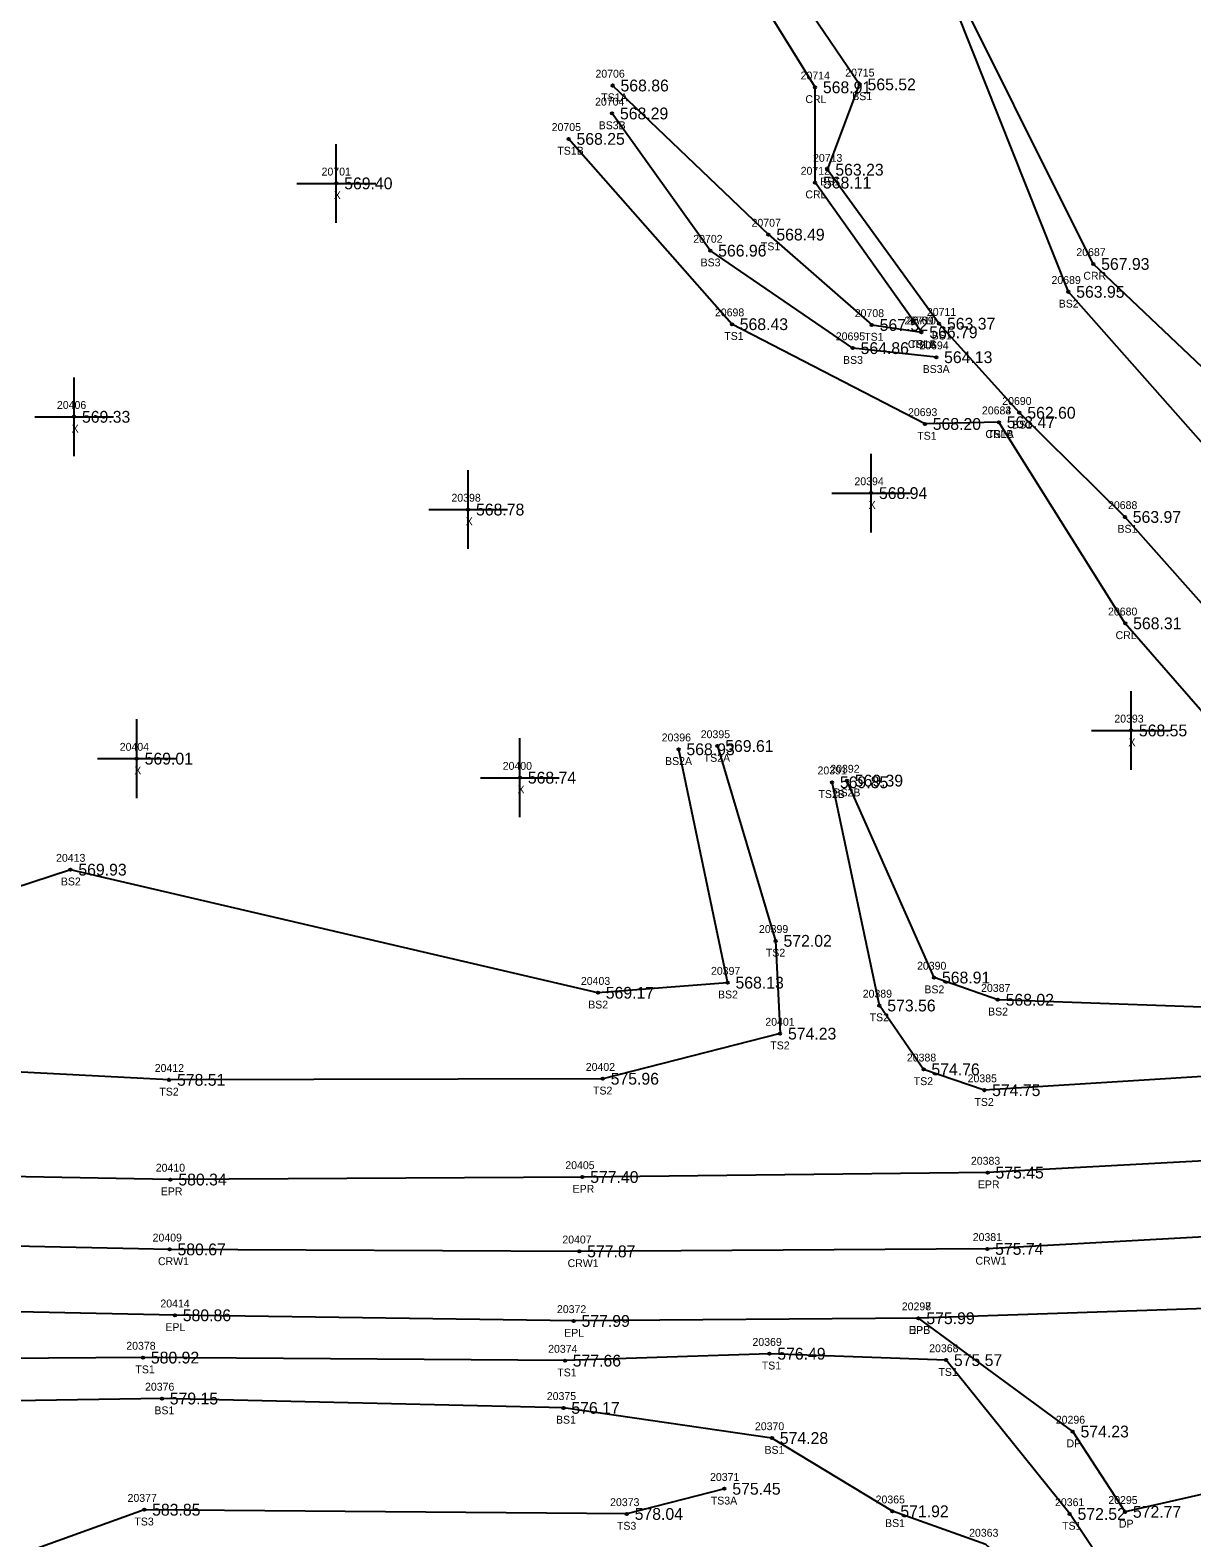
# Model space of a CAD drawing. Extents: x 1530159 to 1531652, y 877045 to 877724.
# Drawn here: x 1530693.4 to 1530840.9, y 877231.5 to 877423 of the extents above; entities that cross this region are included whole.
import ezdxf

# ---------------------------------------------------------------- set-up
doc = ezdxf.new("R2010")
doc.units = 0
for name, color, linetype in [('RD_DTM_BkLn1', 7, 'Continuous'), ('RD_DTM_BkLn2', 7, 'Continuous'), ('RD_DTM_BkLn_txCode', 7, 'Continuous'), ('RD_EX_Driveway', 7, 'Continuous'), ('RD_EX_Driveway_txCode', 7, 'Continuous'), ('RD_EX_H2O', 7, 'Continuous'), ('RD_EX_H2O_txCode', 7, 'Continuous'), ('RD_EX_Misc', 7, 'Continuous'), ('RD_EX_Misc_txCode', 7, 'Continuous'), ('RD_EX_Road', 7, 'Continuous'), ('RD_EX_Road_txCode', 7, 'Continuous'), ('RD_EX_TX_Driveway_ELEV', 7, 'Continuous'), ('RD_EX_TX_H2O_ELEV', 7, 'Continuous'), ('RD_EX_TX_Misc_ELEV', 7, 'Continuous'), ('RD_EX_TX_Road_ELEV', 7, 'Continuous'), ('RD_HC_Survey_ELEV', 7, 'Continuous'), ('RD_HC_Survey_txCode', 7, 'Continuous'), ('RD_SMD_Locator', 7, 'Continuous')]:
    doc.layers.add(name, color=color, linetype=linetype)

msp = doc.modelspace()

# ---------------------------------------------------------------- linework, layer by layer
at = {"layer": 'RD_DTM_BkLn1'}
msp.add_lwpolyline([(1530865.56, 877271.01), (1530814.96, 877268.2), (1530763.15, 877267.89), (1530711.13, 877268.14), (1530659.67, 877269.22), (1530608.85, 877271.65), (1530559.07, 877277.33), (1530509.18, 877284.07), (1530458.44, 877292.62), (1530408.04, 877304.59), (1530358.54, 877316.67), (1530308.57, 877330.02), (1530250.23, 877350.32), (1530188.17, 877372.62)], dxfattribs=at)
at = {"layer": 'RD_DTM_BkLn2'}
for points in [[(1530978.51, 877193.14), (1530957.83, 877217.34), (1530939.69, 877236.27), (1530919.92, 877243.6), (1530901.7, 877240.19), (1530890.91, 877253.72), (1530883.61, 877289.66), (1530871.34, 877309.06), (1530854.23, 877336.62), (1530832.44, 877361.15), (1530819.05, 877374.38), (1530808.85, 877385.69), (1530794.67, 877405.25), (1530798.76, 877416.08), (1530761.4, 877471.05), (1530729.88, 877527.47), (1530702.64, 877561.57), (1530689.57, 877599.12), (1530672.36, 877642.36), (1530634.08, 877679.71), (1530613.02, 877709.76)], [(1530924.53, 877258.32), (1530897.88, 877293.87), (1530872.66, 877332.29), (1530858.92, 877351.67), (1530825.26, 877389.74), (1530809.31, 877429.86), (1530783.89, 877460.41), (1530770.73, 877490.54), (1530744.62, 877534.44), (1530713.25, 877572.12), (1530699.86, 877617.16), (1530688.52, 877646.11), (1530631.13, 877700.3)], [(1530767.39, 877415.94), (1530787.18, 877397.01), (1530800.3, 877385.53), (1530806.6, 877384.6)], [(1530808.48, 877381.44), (1530797.88, 877382.59), (1530779.79, 877394.97), (1530767.32, 877412.39)], [(1530816.44, 877373.18), (1530807.04, 877372.96), (1530782.53, 877385.63), (1530761.8, 877409.16)], [(1530846.55, 877195.51), (1530836.44, 877218.02), (1530825.43, 877234.54), (1530809.73, 877254.08), (1530787.3, 877254.89), (1530761.32, 877254.01), (1530707.75, 877254.4), (1530659.82, 877254.09), (1530608.22, 877255.41), (1530556.36, 877261.96), (1530505.86, 877268.16), (1530455.53, 877277.54), (1530404.07, 877287.69), (1530355.59, 877301.63), (1530305.18, 877312.26), (1530242.86, 877334.32), (1530183.05, 877357.3)], [(1530843.03, 877194.57), (1530830.04, 877216.97), (1530814.8, 877230.65), (1530802.93, 877234.88), (1530787.62, 877244.18), (1530761.15, 877248.01), (1530710.15, 877249.2), (1530659.29, 877248.38), (1530607.91, 877252.81), (1530555.6, 877260.07), (1530504.64, 877266.43), (1530454.3, 877275.47), (1530403.13, 877286.43), (1530354.95, 877299.51), (1530304.97, 877310.18), (1530241.94, 877332.54), (1530182.43, 877355.46)], [(1530775.76, 877331.65), (1530781.99, 877302.01), (1530765.52, 877300.73), (1530698.54, 877316.36), (1530664, 877305.04), (1530603.15, 877311.86), (1530587.05, 877355.57)], [(1530780.69, 877332.06), (1530788.09, 877307.32), (1530788.66, 877295.54), (1530766.14, 877289.81), (1530711.07, 877289.67), (1530661.26, 877292.24), (1530608.81, 877294.06), (1530562.73, 877296.61), (1530511.3, 877298), (1530460.71, 877306.98), (1530411.43, 877318.55), (1530362.64, 877330.57), (1530303.69, 877348.12), (1530304.27, 877353.11), (1530308.16, 877353.44)], [(1530875.94, 877287), (1530863.31, 877291.42), (1530814.58, 877288.36), (1530806.87, 877291), (1530801.27, 877299.11), (1530795.25, 877327.46)], [(1530862.42, 877298.16), (1530816.3, 877299.84), (1530808.21, 877302.66), (1530797.14, 877327.67)], [(1530781.59, 877237.74), (1530769.19, 877234.54), (1530707.91, 877235.08), (1530658.9, 877217.43), (1530601.44, 877222.78), (1530585.47, 877250.74), (1530554.71, 877252.85), (1530502.71, 877258.91), (1530451.66, 877269.63), (1530401.38, 877279.82), (1530344.51, 877291.95), (1530339.77, 877285.8), (1530357.81, 877267.08), (1530377.75, 877244.03)]]:
    msp.add_lwpolyline(points, dxfattribs=at)
at = {"layer": 'RD_EX_Driveway'}
msp.add_lwpolyline([(1530852.87, 877260.97), (1530843.68, 877248.24), (1530843.67, 877237.37), (1530832.46, 877234.81), (1530825.81, 877245.01), (1530806.23, 877259.4)], dxfattribs=at)
at = {"layer": 'RD_EX_H2O'}
for points in [[(1530806.6, 877384.6), (1530793.1, 877403.61), (1530793.09, 877415.71), (1530759.45, 877470.01), (1530725.85, 877522.95), (1530701.01, 877557.5), (1530682.02, 877598.59), (1530669.08, 877633.76), (1530634.33, 877678.03), (1530609.31, 877709.18)], [(1530922.5, 877289.86), (1530895.04, 877301.24), (1530872.88, 877333.85), (1530860.22, 877363.17), (1530828.43, 877393.28), (1530808.3, 877433.62), (1530784.24, 877462.07), (1530773.36, 877492.12), (1530746.47, 877535.88), (1530723.52, 877580.98), (1530706.2, 877619.34), (1530689.1, 877649.27), (1530633.62, 877702.51)], [(1530972.1, 877196.48), (1530925.87, 877229.17), (1530918.34, 877241.35), (1530897.53, 877235.99), (1530881.25, 877248.19), (1530880.72, 877258.4), (1530879.1, 877290.18), (1530865.94, 877309.23), (1530832.49, 877347.64), (1530816.44, 877373.18)]]:
    msp.add_lwpolyline(points, dxfattribs=at)
at = {"layer": 'RD_EX_Misc'}
for p, q in [((1530732.3, 877398.51), (1530732.3, 877408.51)), ((1530727.3, 877403.51), (1530737.3, 877403.51)), ((1530699, 877368.87), (1530699, 877378.87)), ((1530694, 877373.87), (1530704, 877373.87)), ((1530800.21, 877359.18), (1530800.21, 877369.18)), ((1530749.04, 877357.09), (1530749.04, 877367.09)), ((1530795.21, 877364.18), (1530805.21, 877364.18)), ((1530744.04, 877362.09), (1530754.04, 877362.09)), ((1530833.22, 877329.04), (1530833.22, 877339.04)), ((1530706.96, 877325.46), (1530706.96, 877335.46)), ((1530828.22, 877334.04), (1530838.22, 877334.04)), ((1530755.62, 877323.04), (1530755.62, 877333.04)), ((1530701.96, 877330.46), (1530711.96, 877330.46)), ((1530750.62, 877328.04), (1530760.62, 877328.04))]:
    msp.add_line(p, q, dxfattribs=at)
at = {"layer": 'RD_EX_Road'}
for points in [[(1530865.35, 877283.66), (1530865.36, 877280.61), (1530815.01, 877277.89), (1530763.54, 877277.33), (1530711.24, 877277.01), (1530660.64, 877277.93), (1530609.51, 877281.74), (1530559.88, 877286.96), (1530511.03, 877294.4), (1530460.35, 877303.35), (1530410.49, 877314.53), (1530361.04, 877326.77), (1530310.59, 877340.83), (1530305.81, 877342.41), (1530288.71, 877347.95), (1530253.55, 877359.27), (1530192.32, 877382.67)], [(1530866.41, 877261.44), (1530852.87, 877260.97), (1530806.23, 877259.4), (1530762.44, 877259.05), (1530711.8, 877259.77), (1530659.89, 877260.87), (1530608.32, 877263.5), (1530557.85, 877268.33), (1530507.29, 877275.71), (1530456.72, 877284.51), (1530406.3, 877294.52), (1530356.75, 877305.76), (1530307.05, 877320.51), (1530246, 877341.34), (1530185.26, 877363.97)]]:
    msp.add_lwpolyline(points, dxfattribs=at)
at = {"layer": 'RD_SMD_Locator'}
for centre in [(1530767.39, 877415.94), (1530798.76, 877416.08), (1530793.09, 877415.71), (1530767.32, 877412.39), (1530761.8, 877409.16), (1530794.67, 877405.25), (1530732.3, 877403.51), (1530793.1, 877403.61), (1530787.18, 877397.01), (1530779.79, 877394.97), (1530828.43, 877393.28), (1530825.26, 877389.74), (1530782.53, 877385.63), (1530800.3, 877385.53), (1530808.85, 877385.69), (1530806.6, 877384.6), (1530806.6, 877384.6), (1530797.88, 877382.59), (1530808.48, 877381.44), (1530699, 877373.87), (1530819.05, 877374.38), (1530807.04, 877372.96), (1530816.44, 877373.18), (1530816.44, 877373.18), (1530800.21, 877364.18), (1530749.04, 877362.09), (1530832.44, 877361.15), (1530832.49, 877347.64), (1530833.22, 877334.04), (1530775.76, 877331.65), (1530780.69, 877332.06), (1530706.96, 877330.46), (1530755.62, 877328.04), (1530795.25, 877327.46), (1530797.14, 877327.67), (1530698.54, 877316.36), (1530788.09, 877307.32), (1530781.99, 877302.01), (1530808.21, 877302.66), (1530765.52, 877300.73), (1530801.27, 877299.11), (1530816.3, 877299.84), (1530788.66, 877295.54), (1530711.07, 877289.67), (1530766.14, 877289.81), (1530806.87, 877291), (1530814.58, 877288.36), (1530711.24, 877277.01), (1530763.54, 877277.33), (1530815.01, 877277.89), (1530711.13, 877268.14), (1530763.15, 877267.89), (1530814.96, 877268.2), (1530711.8, 877259.77), (1530762.44, 877259.05), (1530806.23, 877259.4), (1530806.23, 877259.4), (1530707.75, 877254.4), (1530761.32, 877254.01), (1530787.3, 877254.89), (1530809.73, 877254.08), (1530710.15, 877249.2), (1530761.15, 877248.01), (1530787.62, 877244.18), (1530825.81, 877245.01), (1530781.59, 877237.74), (1530707.91, 877235.08), (1530769.19, 877234.54), (1530802.93, 877234.88), (1530825.43, 877234.54), (1530832.46, 877234.81)]:
    msp.add_circle(centre, 0.15, dxfattribs=at)

# ---------------------------------------------------------------- texts
at = {"layer": 'RD_DTM_BkLn_txCode'}
for s, p in [('20706', (1530765.21, 877416.94)), ('20715', (1530796.93, 877417.08)), ('20704', (1530765.16, 877413.39)), ('TS1A', (1530765.94, 877413.94)), ('BS1', (1530797.82, 877414.08)), ('20705', (1530759.65, 877410.16)), ('BS3B', (1530765.62, 877410.39)), ('TS1B', (1530760.37, 877407.16)), ('20713', (1530792.84, 877406.25)), ('BS1', (1530793.73, 877403.25)), ('20707', (1530785.03, 877398.01)), ('20702', (1530777.63, 877395.97)), ('TS1', (1530786.22, 877395.01)), ('BS3', (1530778.56, 877392.97)), ('20689', (1530823.12, 877390.74)), ('20698', (1530780.38, 877386.63)), ('20708', (1530798.14, 877386.53)), ('20711', (1530807.3, 877386.69)), ('BS2', (1530824.04, 877387.74)), ('20709', (1530804.44, 877385.6)), ('TS1', (1530781.57, 877383.63)), ('20695', (1530795.73, 877383.59)), ('TS1', (1530799.34, 877383.53)), ('TS1B', (1530805.16, 877382.6)), ('20694', (1530806.34, 877382.44)), ('BS1', (1530807.91, 877383.69)), ('BS3', (1530796.65, 877380.59)), ('BS3A', (1530806.76, 877379.44)), ('20690', (1530816.87, 877375.38)), ('20693', (1530804.9, 877373.96)), ('20684', (1530814.29, 877374.18)), ('TS1', (1530806.08, 877370.96)), ('TS1A', (1530814.99, 877371.18)), ('BS1', (1530818.11, 877372.38)), ('20688', (1530830.3, 877362.15)), ('BS1', (1530831.5, 877359.15)), ('20396', (1530773.62, 877332.65)), ('20395', (1530778.58, 877333.06)), ('BS2A', (1530774.05, 877329.65)), ('TS2A', (1530778.96, 877330.06)), ('20391', (1530793.41, 877328.46)), ('20392', (1530795.03, 877328.67)), ('TS2B', (1530793.53, 877325.46)), ('BS2B', (1530795.44, 877325.67)), ('20413', (1530696.71, 877317.36)), ('BS2', (1530697.32, 877314.36)), ('20399', (1530785.97, 877308.32)), ('TS2', (1530786.85, 877305.32)), ('20397', (1530779.88, 877303.01)), ('20390', (1530806.05, 877303.66)), ('20403', (1530763.36, 877301.73)), ('20389', (1530799.15, 877300.11)), ('BS2', (1530806.98, 877300.66)), ('20387', (1530814.18, 877300.84)), ('BS2', (1530764.29, 877298.73)), ('BS2', (1530780.77, 877300.01)), ('20401', (1530786.78, 877296.54)), ('TS2', (1530800.03, 877297.11)), ('BS2', (1530815.07, 877297.84)), ('TS2', (1530787.41, 877293.54)), ('20412', (1530709.24, 877290.67)), ('20402', (1530763.98, 877290.81)), ('20388', (1530804.76, 877292)), ('TS2', (1530805.63, 877289)), ('20385', (1530812.47, 877289.36)), ('TS2', (1530709.83, 877287.67)), ('TS2', (1530764.9, 877287.81)), ('TS2', (1530813.34, 877286.36)), ('20378', (1530705.63, 877255.4)), ('20374', (1530759.2, 877255.01)), ('20369', (1530785.15, 877255.89)), ('20368', (1530807.59, 877255.08)), ('TS1', (1530706.79, 877252.4)), ('TS1', (1530786.33, 877252.89)), ('TS1', (1530760.36, 877252.01)), ('TS1', (1530808.77, 877252.08)), ('20376', (1530708.01, 877250.2)), ('20375', (1530759.03, 877249.01)), ('BS1', (1530709.2, 877247.2)), ('BS1', (1530760.2, 877246.01)), ('20370', (1530785.46, 877245.18)), ('BS1', (1530786.68, 877242.18)), ('20371', (1530779.76, 877238.74)), ('20377', (1530705.79, 877236.08)), ('20373', (1530767.07, 877235.54)), ('TS3A', (1530779.86, 877235.74)), ('20365', (1530800.79, 877235.88)), ('20361', (1530823.57, 877235.54)), ('TS3', (1530706.66, 877233.08)), ('TS3', (1530767.94, 877232.54)), ('BS1', (1530801.99, 877232.88)), ('20363', (1530812.66, 877231.65)), ('TS1', (1530824.47, 877232.54))]:
    msp.add_text(s, height=1, dxfattribs=at).set_placement(p)
at = {"layer": 'RD_EX_Driveway_txCode'}
for s, p in [('20297', (1530804.11, 877260.4)), ('DPB', (1530804.98, 877257.4)), ('20296', (1530823.67, 877246.01)), ('DP', (1530825.03, 877243.01)), ('20295', (1530830.34, 877235.81)), ('DP', (1530831.68, 877232.81))]:
    msp.add_text(s, height=1, dxfattribs=at).set_placement(p)
at = {"layer": 'RD_EX_H2O_txCode'}
for s, p in [('20714', (1530791.26, 877416.71)), ('CRL', (1530791.87, 877413.71)), ('20712', (1530791.27, 877404.61)), ('CRL', (1530791.87, 877401.61)), ('20687', (1530826.28, 877394.28)), ('CRR', (1530827.17, 877391.28)), ('20710', (1530804.72, 877385.6)), ('CRLA', (1530804.88, 877382.6)), ('20683', (1530814.29, 877374.18)), ('CRLB', (1530814.73, 877371.18)), ('20680', (1530830.3, 877348.64)), ('CRL', (1530831.26, 877345.64))]:
    msp.add_text(s, height=1, dxfattribs=at).set_placement(p)
at = {"layer": 'RD_EX_Misc_txCode'}
for s, p in [('20701', (1530730.43, 877404.51)), ('X', (1530731.98, 877401.51)), ('20406', (1530696.82, 877374.87)), ('X', (1530698.69, 877371.87)), ('20394', (1530798.1, 877365.18)), ('20398', (1530746.92, 877363.09)), ('X', (1530799.9, 877362.18)), ('X', (1530748.73, 877360.09)), ('20393', (1530831.1, 877335.04)), ('20404', (1530704.8, 877331.46)), ('X', (1530832.9, 877332.04)), ('20400', (1530753.43, 877329.04)), ('X', (1530706.65, 877328.46)), ('X', (1530755.31, 877326.04))]:
    msp.add_text(s, height=1, dxfattribs=at).set_placement(p)
at = {"layer": 'RD_EX_Road_txCode'}
for s, p in [('20410', (1530709.37, 877278.01)), ('20405', (1530761.38, 877278.33)), ('20383', (1530812.89, 877278.89)), ('EPR', (1530762.31, 877275.33)), ('EPR', (1530813.78, 877275.89)), ('EPR', (1530710.01, 877275.01)), ('20414', (1530709.96, 877260.77)), ('20372', (1530760.32, 877260.05)), ('20298', (1530804.11, 877260.4)), ('EPL', (1530710.59, 877257.77)), ('EPL', (1530761.24, 877257.05)), ('EPL', (1530805.02, 877257.4))]:
    msp.add_text(s, height=1, dxfattribs=at).set_placement(p)
at = {"layer": 'RD_EX_TX_Driveway_ELEV'}
for s, p in [('575.99', (1530807.23, 877258.65)), ('574.23', (1530826.81, 877244.26)), ('572.77', (1530833.46, 877234.06))]:
    msp.add_text(s, height=1.5, dxfattribs=at).set_placement(p)
at = {"layer": 'RD_EX_TX_H2O_ELEV'}
for s, p in [('568.91', (1530794.09, 877414.96)), ('568.11', (1530794.1, 877402.86)), ('567.93', (1530829.43, 877392.53)), ('566.79', (1530807.6, 877383.85)), ('568.47', (1530817.44, 877372.43)), ('568.31', (1530833.49, 877346.89))]:
    msp.add_text(s, height=1.5, dxfattribs=at).set_placement(p)
at = {"layer": 'RD_EX_TX_Misc_ELEV'}
for s, p in [('568.86', (1530768.39, 877415.19)), ('565.52', (1530799.76, 877415.33)), ('568.29', (1530768.32, 877411.64)), ('568.25', (1530762.8, 877408.41)), ('563.23', (1530795.67, 877404.5)), ('569.40', (1530733.3, 877402.76)), ('568.49', (1530788.18, 877396.26)), ('566.96', (1530780.79, 877394.22)), ('563.95', (1530826.26, 877388.99)), ('568.43', (1530783.53, 877384.88)), ('567.52', (1530801.3, 877384.78)), ('566.79', (1530807.6, 877383.85)), ('563.37', (1530809.85, 877384.94)), ('564.86', (1530798.88, 877381.84)), ('564.13', (1530809.48, 877380.69)), ('569.33', (1530700, 877373.12)), ('568.47', (1530817.44, 877372.43)), ('562.60', (1530820.05, 877373.63)), ('568.20', (1530808.04, 877372.21)), ('568.94', (1530801.21, 877363.43)), ('568.78', (1530750.04, 877361.34)), ('563.97', (1530833.44, 877360.4)), ('568.55', (1530834.22, 877333.29)), ('568.93', (1530776.76, 877330.9)), ('569.61', (1530781.69, 877331.31)), ('569.01', (1530707.96, 877329.71)), ('568.74', (1530756.62, 877327.29)), ('569.85', (1530796.25, 877326.71)), ('569.39', (1530798.14, 877326.92)), ('569.93', (1530699.54, 877315.61)), ('572.02', (1530789.09, 877306.57)), ('568.91', (1530809.21, 877301.91)), ('569.17', (1530766.52, 877299.98)), ('568.13', (1530782.99, 877301.26)), ('573.56', (1530802.27, 877298.36)), ('568.02', (1530817.3, 877299.09)), ('574.23', (1530789.66, 877294.79)), ('574.76', (1530807.87, 877290.25)), ('578.51', (1530712.07, 877288.92)), ('575.96', (1530767.14, 877289.06)), ('574.75', (1530815.58, 877287.61)), ('580.92', (1530708.75, 877253.65)), ('576.49', (1530788.3, 877254.14)), ('577.66', (1530762.32, 877253.26)), ('575.57', (1530810.73, 877253.33)), ('579.15', (1530711.15, 877248.45)), ('576.17', (1530762.15, 877247.26)), ('574.28', (1530788.62, 877243.43)), ('575.45', (1530782.59, 877236.99)), ('583.85', (1530708.91, 877234.33)), ('578.04', (1530770.19, 877233.79)), ('571.92', (1530803.93, 877234.13)), ('572.52', (1530826.43, 877233.79))]:
    msp.add_text(s, height=1.5, dxfattribs=at).set_placement(p)
at = {"layer": 'RD_EX_TX_Road_ELEV'}
for s, p in [('577.40', (1530764.54, 877276.58)), ('575.45', (1530816.01, 877277.14)), ('580.34', (1530712.24, 877276.26)), ('580.86', (1530712.8, 877259.02)), ('577.99', (1530763.44, 877258.3)), ('575.99', (1530807.23, 877258.65))]:
    msp.add_text(s, height=1.5, dxfattribs=at).set_placement(p)
at = {"layer": 'RD_HC_Survey_ELEV'}
for s, p in [('580.67', (1530712.13, 877267.39)), ('577.87', (1530764.15, 877267.14)), ('575.74', (1530815.96, 877267.45))]:
    msp.add_text(s, height=1.5, dxfattribs=at).set_placement(p)
at = {"layer": 'RD_HC_Survey_txCode'}
for s, p in [('20409', (1530708.97, 877269.14)), ('20407', (1530761, 877268.89)), ('20381', (1530813.12, 877269.2)), ('CRW1', (1530709.65, 877266.14)), ('CRW1', (1530761.67, 877265.89)), ('CRW1', (1530813.47, 877266.2))]:
    msp.add_text(s, height=1, dxfattribs=at).set_placement(p)

doc.saveas('drawing.dxf')
